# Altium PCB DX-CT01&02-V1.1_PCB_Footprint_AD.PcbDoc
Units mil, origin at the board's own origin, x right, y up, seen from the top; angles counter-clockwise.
Board outline 6000 x 4000 mil, 2 copper layers (Top Layer, Bottom Layer); 1 components, 0 nets, 9 pads, 0 vias.
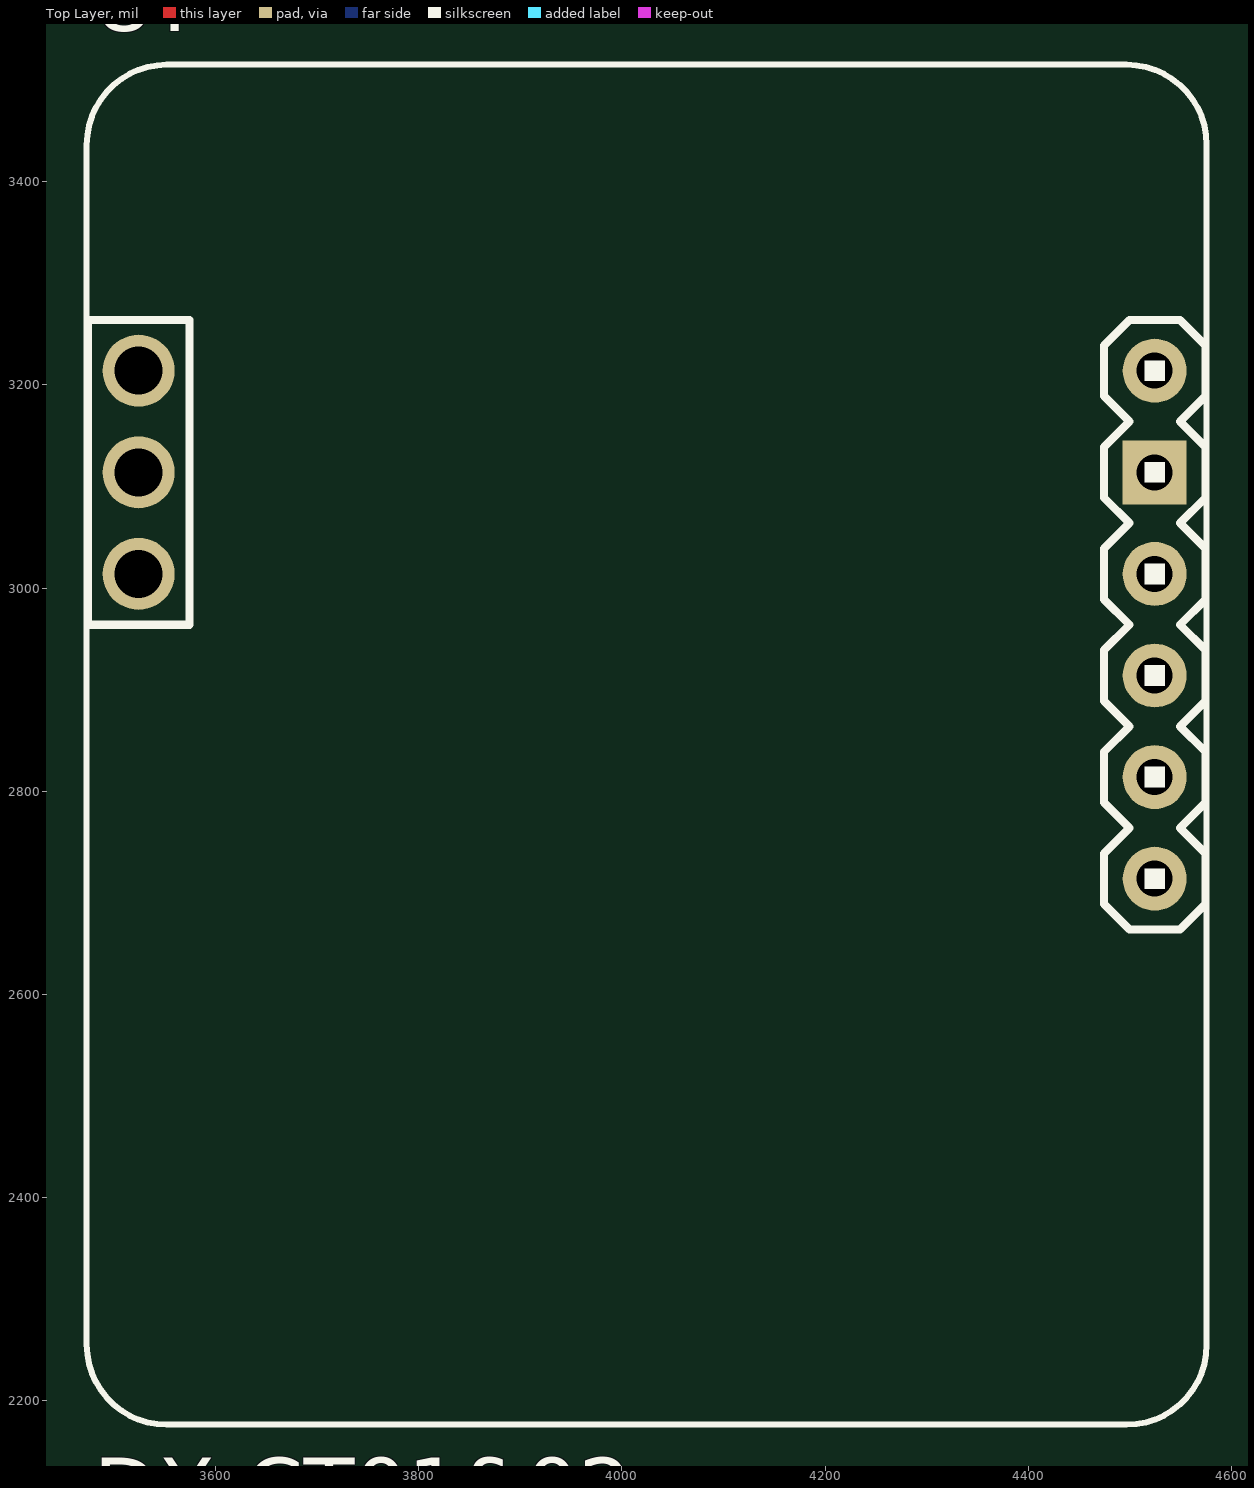
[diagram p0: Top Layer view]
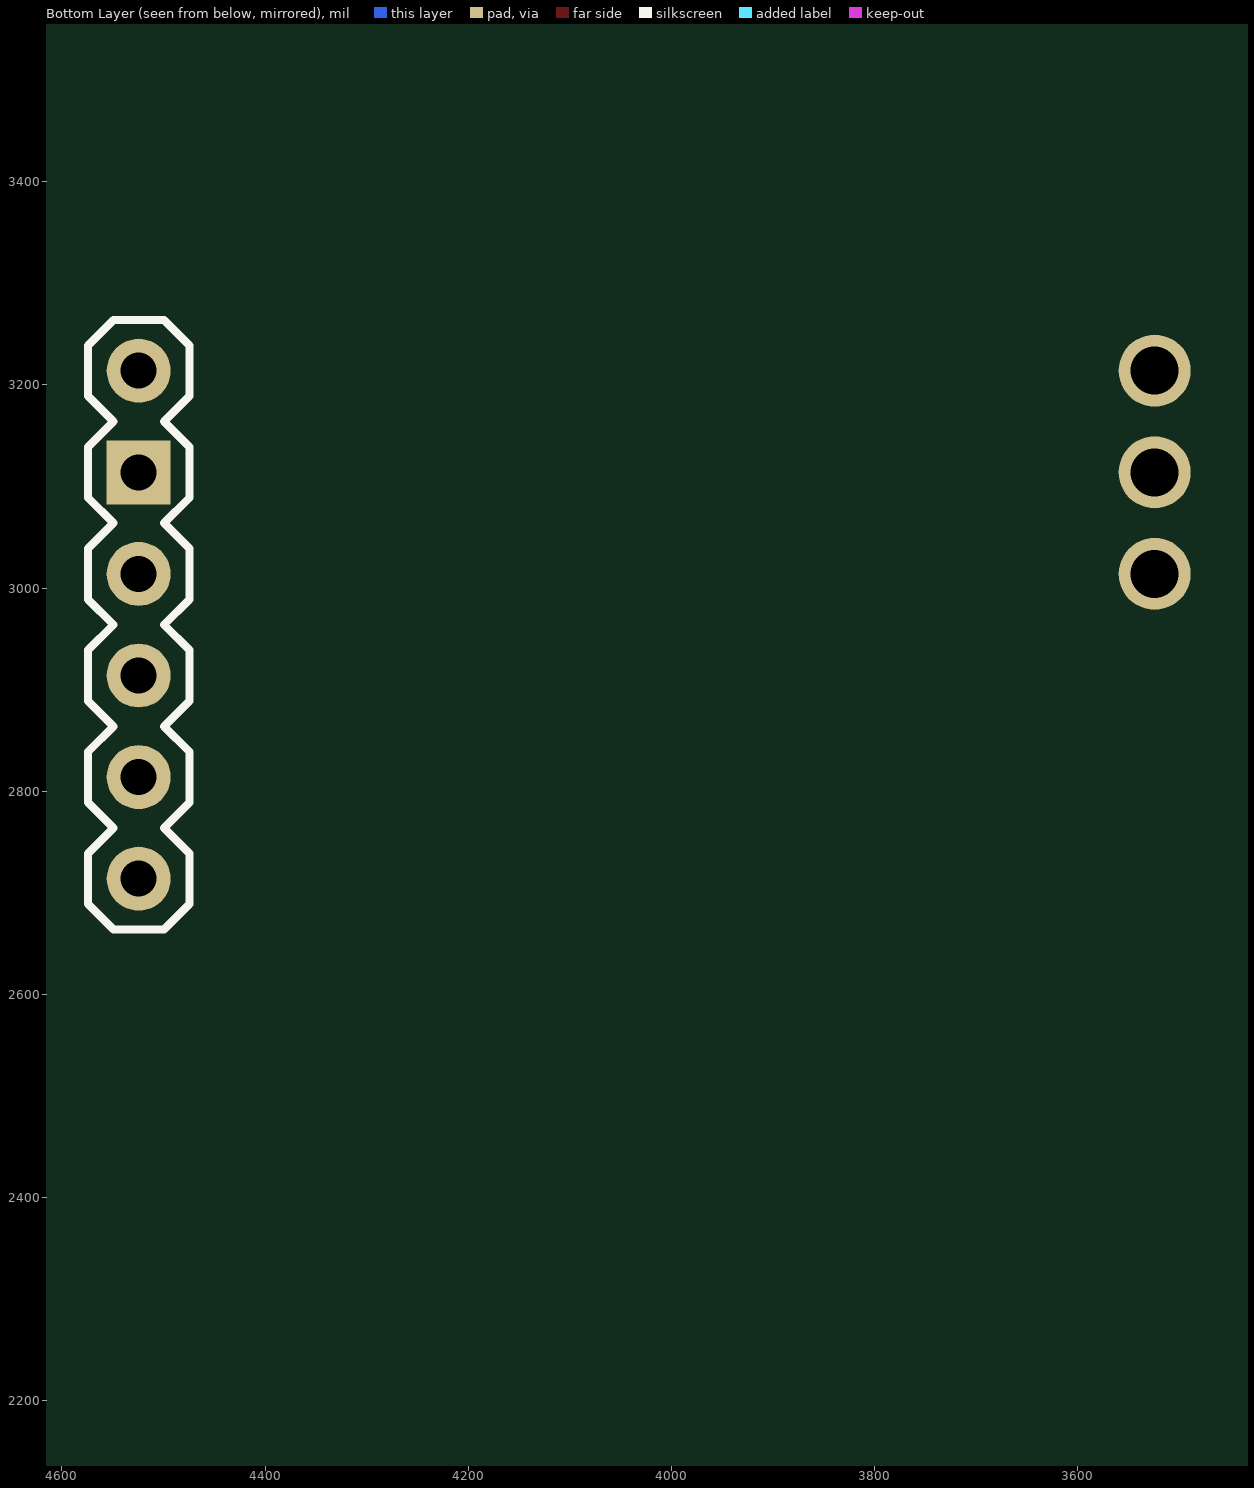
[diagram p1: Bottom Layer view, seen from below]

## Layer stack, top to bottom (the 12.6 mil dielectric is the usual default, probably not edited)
Top Solder: solder mask 0.4, Solder Resist, Dk 3.5
Top Layer: signal copper 1.4
Dielectric 1: dielectric 12.6, FR-4, Dk 4.8
Bottom Layer: signal copper 1.4
Bottom Solder: solder mask 0.4, Solder Resist, Dk 3.5

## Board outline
1000,1000 7000,1000 7000,5000 1000,5000

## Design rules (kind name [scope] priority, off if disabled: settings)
Clearance [All] p1: gap=10 ignorepadtopadclearanceinfootprint=FALSE except(0: Arc-Hole Track-Hole SMDPad-Hole THPad-Hole Via-Hole Fill-Hole Poly-Hole Region-Hole Text-Hole)
PolygonConnect [All] p1: connectstyle=Relief reliefconductorwidth=10 reliefentries=4 polygonreliefangle="90 Angle" airgapwidth=10
RoutingVias [All] p1: holewidth=28 width=50 viastyle="Through Hole" minholewidth=28 minwidth=50 maxholewidth=28 maxwidth=50
SolderMaskExpansion [All] p1: expansion=4 istentingtop=FALSE
Width [All] p1: maxlimit=10 minlimit=10 preferedwidth=10
30 further rules are at their usual default settings.

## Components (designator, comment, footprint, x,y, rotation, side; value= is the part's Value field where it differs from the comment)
U? "DX-CT01&02" CT01 4024.43,2176.46 r0 top

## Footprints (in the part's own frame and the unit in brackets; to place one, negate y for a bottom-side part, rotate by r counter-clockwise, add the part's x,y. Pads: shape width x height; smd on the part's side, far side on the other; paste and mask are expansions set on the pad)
CT01 [mm]
  round 1.6 hole 0.9: 1(12.7,13.65) 2(12.7,16.19) 3(12.7,18.73) 4(12.7,21.27) 6(12.7,26.35)
  rect 1.6x1.6 hole 0.9: 5(12.7,23.81)
  round 1.8 hole 1.2: 7(-12.7,26.35) 8(-12.7,23.81) 9(-12.7,21.27)
  silkscreen extent -14,0 14,34

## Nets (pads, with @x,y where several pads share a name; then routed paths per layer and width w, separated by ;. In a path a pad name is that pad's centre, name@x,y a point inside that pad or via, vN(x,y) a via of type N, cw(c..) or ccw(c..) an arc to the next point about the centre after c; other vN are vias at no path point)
pads on no net: U?.1 U?.2 U?.3 U?.4 U?.5 U?.6 U?.7 U?.8 U?.9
